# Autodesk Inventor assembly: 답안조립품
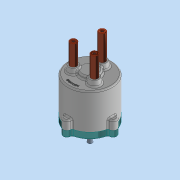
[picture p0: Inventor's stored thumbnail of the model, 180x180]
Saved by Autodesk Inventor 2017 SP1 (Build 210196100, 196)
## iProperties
Part Number: 답안조립품
Material: 일반
Document SubType Name: Assembly
Designer: MRC
Mass: 1236.63 g
Surface Area: 1770.11 cm^2
Volume: 433.787 cm^3
Density: 2.85077 g/cm^3
Author: MRC
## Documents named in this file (14)
- C:\Users\MRC\Desktop\610708V1009\답안조립품.iam
- C:\Users\MRC\Desktop\610708V1009\본체.ipt
- C:\Users\MRC\Desktop\610708V1009\가변스프링1.ipt
- C:\Users\MRC\Desktop\610708V1009\가변스프링2.ipt
- C:\Users\MRC\Desktop\610708V1009\가변스프링3.ipt
- C:\Users\MRC\Desktop\610708V1009\멈춤링 10 x 1.ipt
- C:\Users\MRC\Desktop\610708V1009\멈춤링 22 x 1.2.ipt
- C:\Users\MRC\Desktop\610708V1009\메인 축.ipt
- C:\Users\MRC\Desktop\610708V1009\베어링 NA 4900.ipt
- C:\Users\MRC\Desktop\610708V1009\볼트 M5.ipt
- C:\Users\MRC\Desktop\610708V1009\슬라이드 축.ipt
- C:\Users\MRC\Desktop\610708V1009\오일실.ipt
- C:\Users\MRC\Desktop\610708V1009\커버.ipt
- C:\Users\MRC\Desktop\610708V1009\판캠.ipt
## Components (3 placed, 3 different names)
1. 가변스프링1:1
2. 가변스프링2:1
3. 가변스프링3:1
